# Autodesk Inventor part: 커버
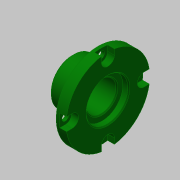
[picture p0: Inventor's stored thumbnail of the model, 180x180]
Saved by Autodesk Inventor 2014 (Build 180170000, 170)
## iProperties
Created: 2019-10
Part Number: 커버
Material: 알루미늄 6061
Document SubType Name: Modeling
Designer: mduedu
Density: 1 g/cm^3
Appearance: 진녹색
Author: mduedu
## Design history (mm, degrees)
sketch "스케치1"
  geometry: L1 (0, 0)-(-18, 0); L2 (-18, 0)-(-18, 11.5); L3 (-18, 11.5)-(-5, 11.5); L4 (-5, 11.5)-(-5, 21); L5 (-5, 21)-(0, 21); L6 (0, 21)-(0, 0)
  constraints: 12 end point, 3 parallel, 2 perpendicular, 1 horizontal
  dimensions: "d0" = 18 distance of L1.start L1.end; "d1" = 42 diameter of L5 L1; "d2" = 23 diameter of L3 L1; "d3" = 13 distance of L2.end L3.end
revolve "회전1" sketch "스케치1" stored, may be unused: angle "d4" = 90 deg
hole "구멍1" diameter "d7" = 15; stored, may be unused: countersink angle "d11" = 90 deg, drill point angle "d13" = 118 deg; dims "d5" = 10, "d6" = 10, "d8" = 6, "d9" = 21, "d10" = 3, "d12" = 8
chamfer "모따기1" distance "d14" = 1; stored, may be unused: second distance "d15" = 2, angle "d16" = 45 deg
sketch "스케치2" dims "d17" = 36
  geometry: 6 further points
  constraints: 2 vertical alignment, 1 coincident, 7 other
  dimensions: "d20" = 360 deg dimension on point (0, 0) point (0, 18) (derived)
sketch "스케치3"
  geometry: 4 further points
  constraints: 4 other
hole "구멍2" sketch "스케치3" at (-18, 0), (0, -18), (18, 0), (0, 18) diameter "d22" = 3.4; stored, may be unused: countersink angle "d26" = 90 deg, drill point angle "d28" = 0 deg; dims "d23" = 6, "d24" = 6.5, "d25" = 3.4, "d27" = 8
sketch "스케치4"
  geometry: L1 (-21.25, 20.747)-(-21.25, 18); L2 (-14.75, 18)-(-14.75, 20.747); A1 r 3.25 centre (-18, 18) between (-19.349, 20.957) and (-16.651, 20.957) reference; A2 r 21 centre (-18, 0) between (-19.349, 20.957) and (-38.957, 1.349) reference; A3 r 21 centre (-18, 0) between (2.957, 1.349) and (-16.651, 20.957) reference; A4 r 21 centre (-18, 0) between (-14.75, 20.747) and (-21.25, 20.747); A5 r 3.25 centre (-18, 18) between (-21.25, 18) and (-14.75, 18); 1 further point
  constraints: 8 point on circle, 4 end point, 2 centre point, 2 coincident, 2 tangent, 1 parallel, 1 vertical
extrude "돌출1" cut sketch "스케치4" stored distance "d29" = 10; taper "d30" = 0 deg
chamfer "모따기3" distance "d37" = 0.5; stored, may be unused: second distance "d38" = 2, angle "d39" = 45 deg
chamfer "모따기4" distance "d40" = 0.5; stored, may be unused: second distance "d41" = 2, angle "d42" = 45 deg
node "솔리드1"
pattern_circular "원형 패턴1" dims angle "d32" = 360 deg
